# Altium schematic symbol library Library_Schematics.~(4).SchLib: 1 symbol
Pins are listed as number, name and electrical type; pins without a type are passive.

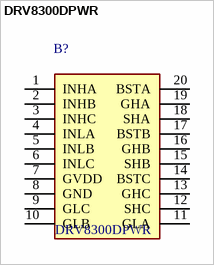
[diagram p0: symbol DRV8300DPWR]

## DRV8300DPWR
designator B?
Gate Drivers 100-V max simple 3-phase gate driver with bootstrap diodes 20-TSSOP -40 to 125; Manufacturer_Name: Texas Instruments; Geometry.Height: 1.2mm
footprint SOP65P640X120-20N
pins: 1 INHA, 2 INHB, 3 INHC, 4 INLA, 5 INLB, 6 INLC, 7 GVDD, 8 GND, 9 GLC, 10 GLB, 11 GLA, 12 SHC, 13 GHC, 14 BSTC, 15 SHB, 16 GHB, 17 BSTB, 18 SHA, 19 GHA, 20 BSTA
